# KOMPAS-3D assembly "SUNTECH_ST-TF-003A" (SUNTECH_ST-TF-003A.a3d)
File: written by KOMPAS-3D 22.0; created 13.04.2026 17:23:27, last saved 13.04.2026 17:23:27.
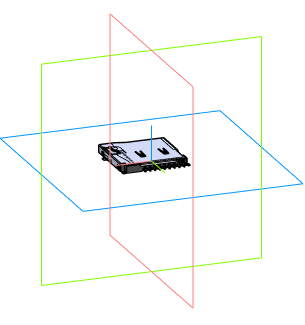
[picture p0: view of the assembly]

Document properties: Автор: Andrey; Полное имя файла: C:\Users\User1\Documents\SUNTECH_ST-TF-003A.a3d

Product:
- Component [detail]: ST-TF-003A  | qty 1  | source file: ST-TF-003A.m3d
- Part/product: SUNTECH_ST-TF-003A
    Комментарий: SUNTECH_ST-TF-003A

Referenced files in C:\Users\User1\Documents\: ST-TF-003A.m3d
